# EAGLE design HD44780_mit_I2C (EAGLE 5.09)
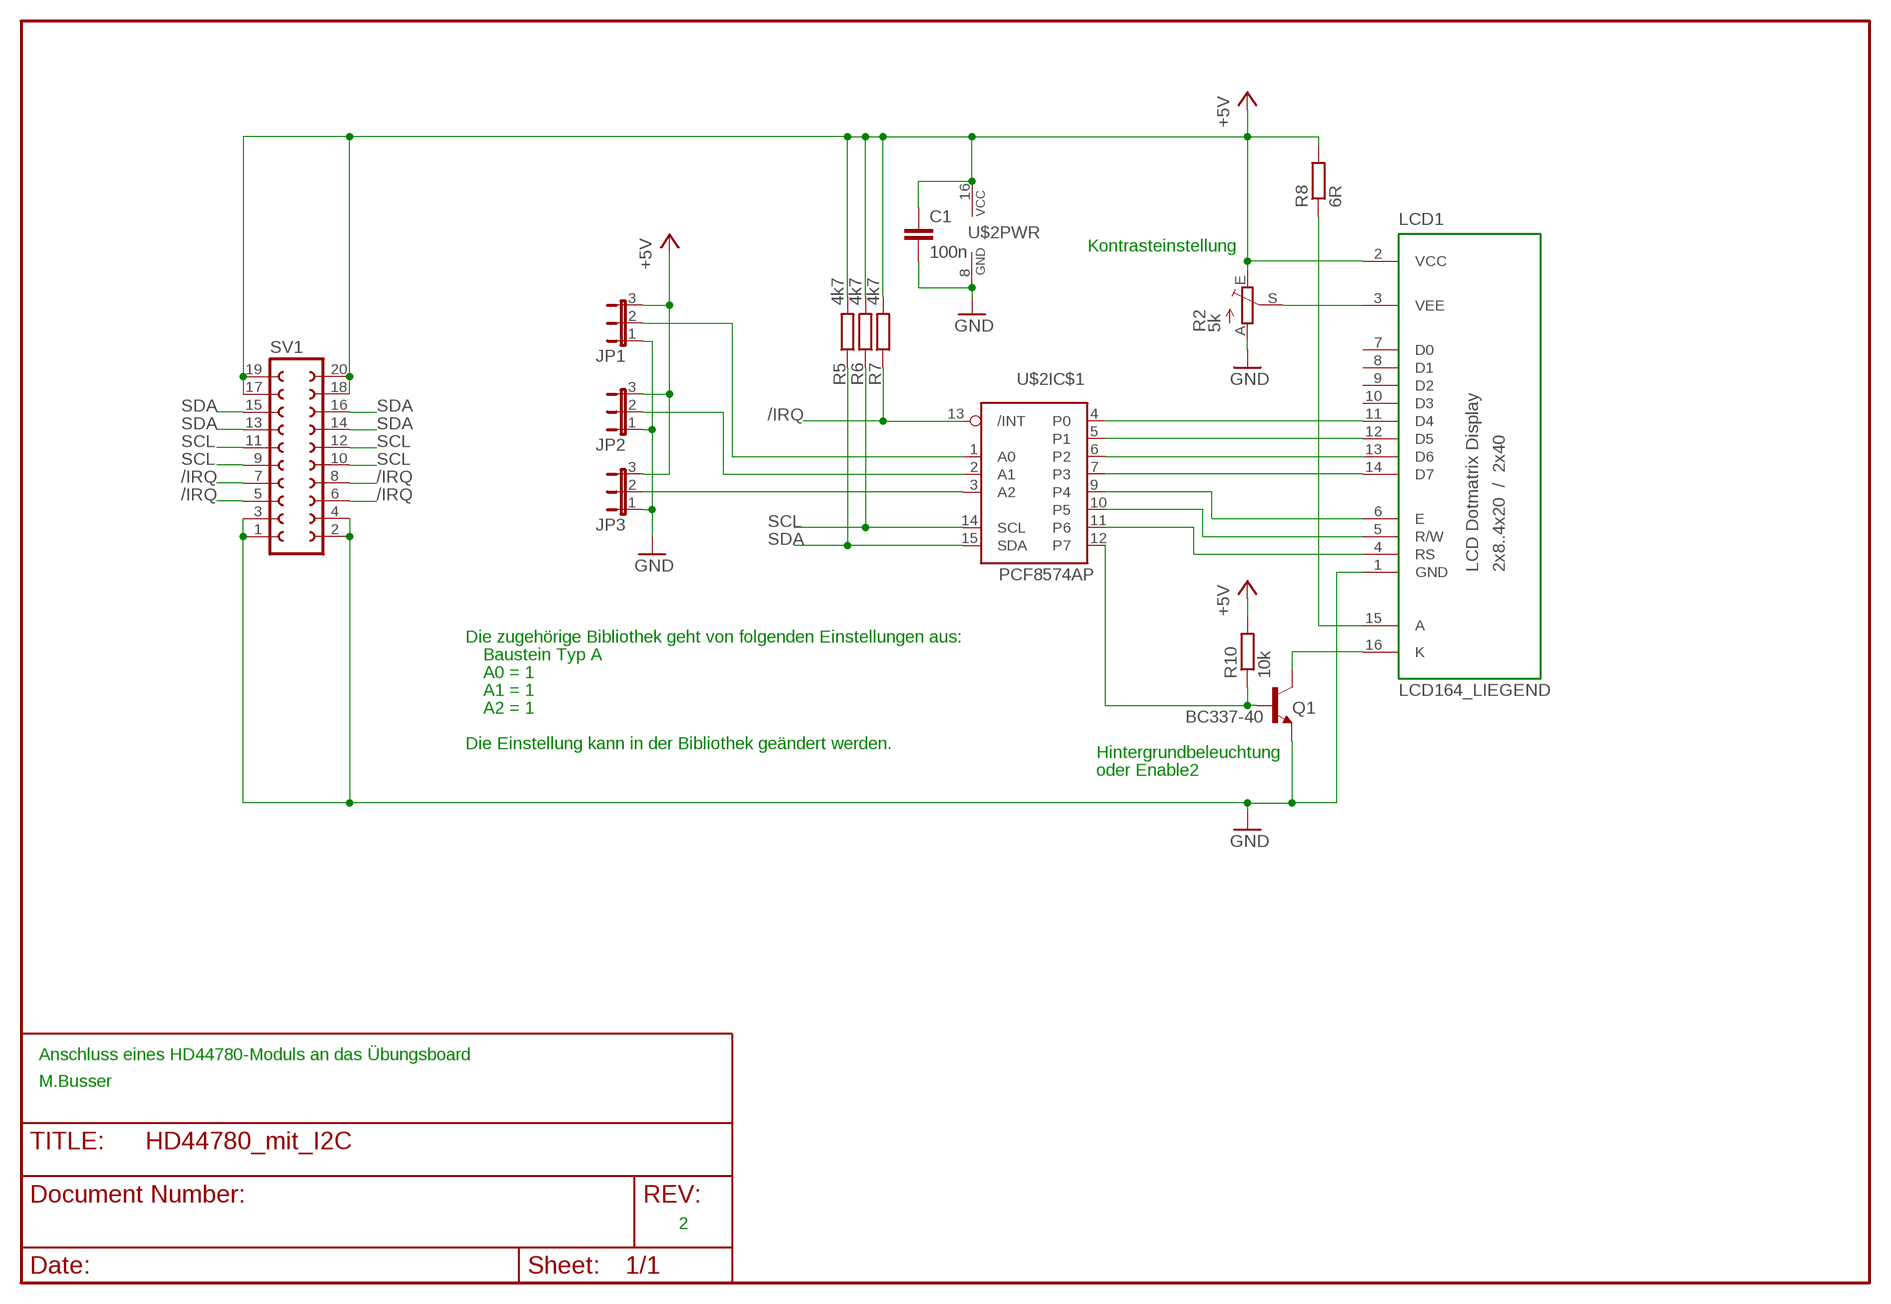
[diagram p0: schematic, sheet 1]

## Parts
C1  100n  C-EU050-025X075  [C050-025X075]
JP1  JP2E  [JP2]
JP2  JP2E  [JP2]
JP3  JP2E  [JP2]
LCD1  LCD164_LIEGEND  [LCD_164_LIEGEND]
Q1  BC337-40  [TO92]
R2  5k  TRIM_EU-B90P  [SP19L]
R5  4k7  R-EU_0207/10  [0207/10]
R6  4k7  R-EU_0207/10  [0207/10]
R7  4k7  R-EU_0207/10  [0207/10]
R8  6R  R-EU_0207/10  [0207/10]
R10  10k  R-EU_0207/10  [0207/10]
SV1  FE10-2  [FE10-2]
U$2  PCF8574AP  [DIL16]

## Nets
+5V: C1.1 JP1.3 JP2.3 JP3.3 LCD1.2(VCC) R2.E R5.2 R6.2 R7.2 R8.2 R10.2 SV1.17 SV1.18 SV1.19 SV1.20 U$2.16(PWR:VCC)
/IRQ: R7.1 SV1.5 SV1.6 SV1.7 SV1.8 U$2.13(IC$1:/INT)
A0: JP1.2 U$2.1(IC$1:A0)
A1: JP2.2 U$2.2(IC$1:A1)
A2: JP3.2 U$2.3(IC$1:A2)
GND: C1.2 JP1.1 JP2.1 JP3.1 LCD1.1(GND) Q1.1(E) R2.A SV1.1 SV1.2 SV1.3 SV1.4 U$2.8(PWR:GND)
N$1: LCD1.3(VEE) R2.S
N$2: LCD1.15(A) R8.1
N$3: LCD1.16(K) Q1.3(C)
N$5: LCD1.11(D4) U$2.4(IC$1:P0)
N$6: Q1.2(B) R10.1 U$2.12(IC$1:P7)
N$7: LCD1.4(RS) U$2.11(IC$1:P6)
N$11: LCD1.12(D5) U$2.5(IC$1:P1)
N$12: LCD1.13(D6) U$2.6(IC$1:P2)
N$13: LCD1.14(D7) U$2.7(IC$1:P3)
N$15: LCD1.6(E) U$2.9(IC$1:P4)
N$16: LCD1.5(R/W) U$2.10(IC$1:P5)
SCL: R6.1 SV1.9 SV1.10 SV1.11 SV1.12 U$2.14(IC$1:SCL)
SDA: R5.1 SV1.13 SV1.14 SV1.15 SV1.16 U$2.15(IC$1:SDA)
Unconnected: LCD1.7(D0) LCD1.8(D1) LCD1.9(D2) LCD1.10(D3)

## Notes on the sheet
- Kontrasteinstellung
- Die zugehörige Bibliothek geht von folgenden Einstellungen aus:
- Baustein Typ A
- A0 = 1
- A1 = 1
- A2 = 1
- Die Einstellung kann in der Bibliothek geändert werden.
- Hintergrundbeleuchtung
- oder Enable2
- Anschluss eines HD44780-Moduls an das Übungsboard
- M.Busser
- 2

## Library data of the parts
C1 = bbstghs:C-EU: CAPACITOR, European symbol
JP1-JP3 = jumper:JP2E: JUMPER
LCD1 = ibb:LCD164_LIEGEND
Q1 = bbstghs:BC337*: NPN Transistor
R2 = pot:TRIM_EU-: POTENTIOMETER
R5-R8 R10 = bbstghs:R-EU_: RESISTOR, European symbol
SV1 = con-lsta:FE10-2: FEMALE HEADER
U$2 = i2c:PCF8574: Remote 8-Bit I/O Expander for I²C Bus

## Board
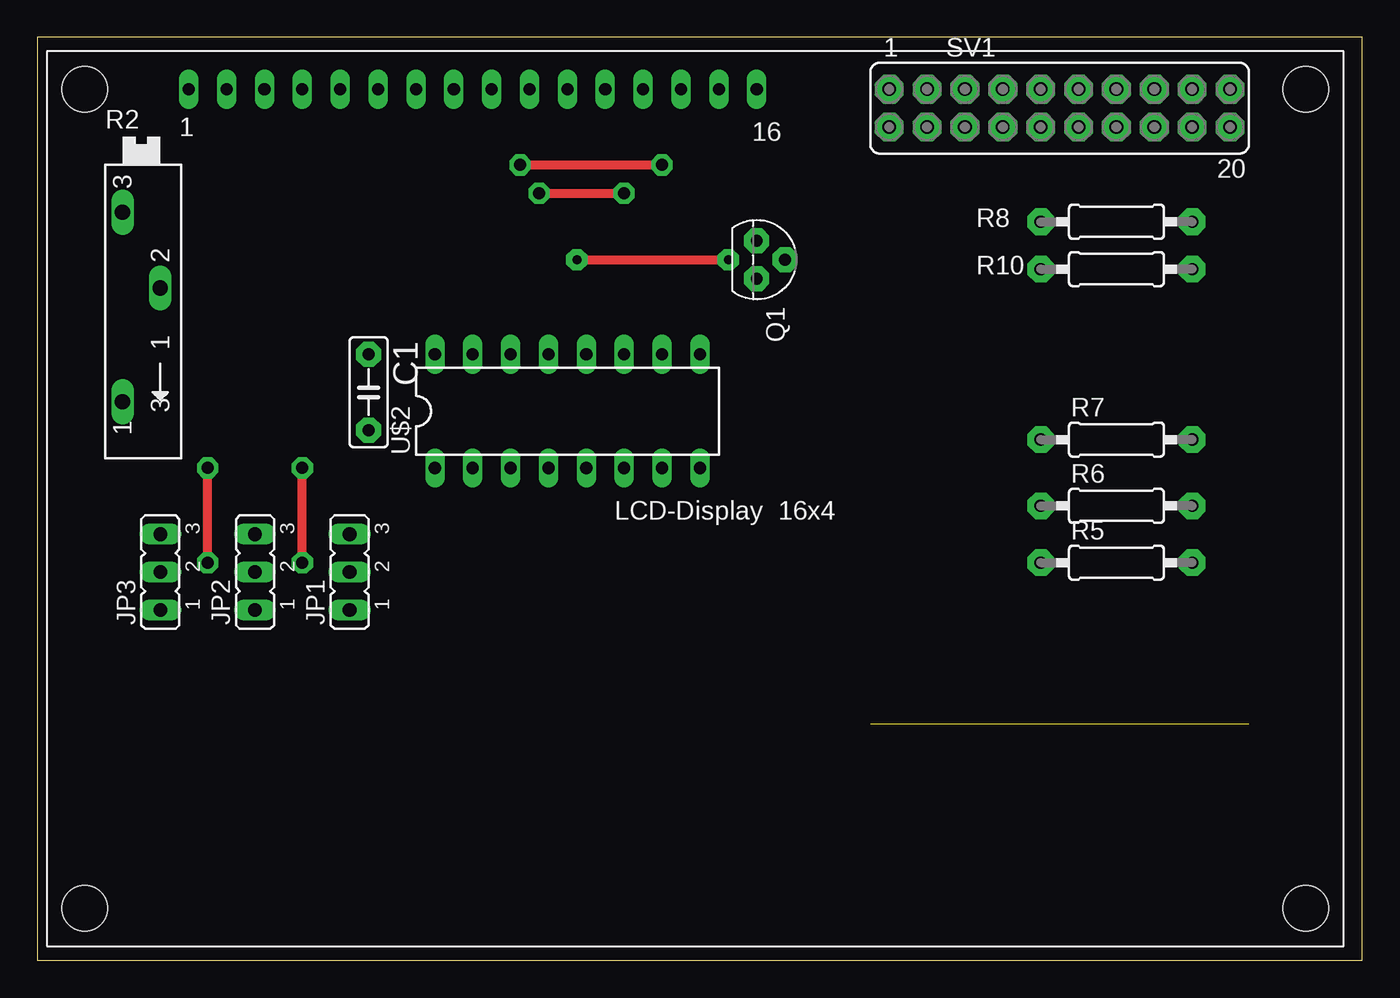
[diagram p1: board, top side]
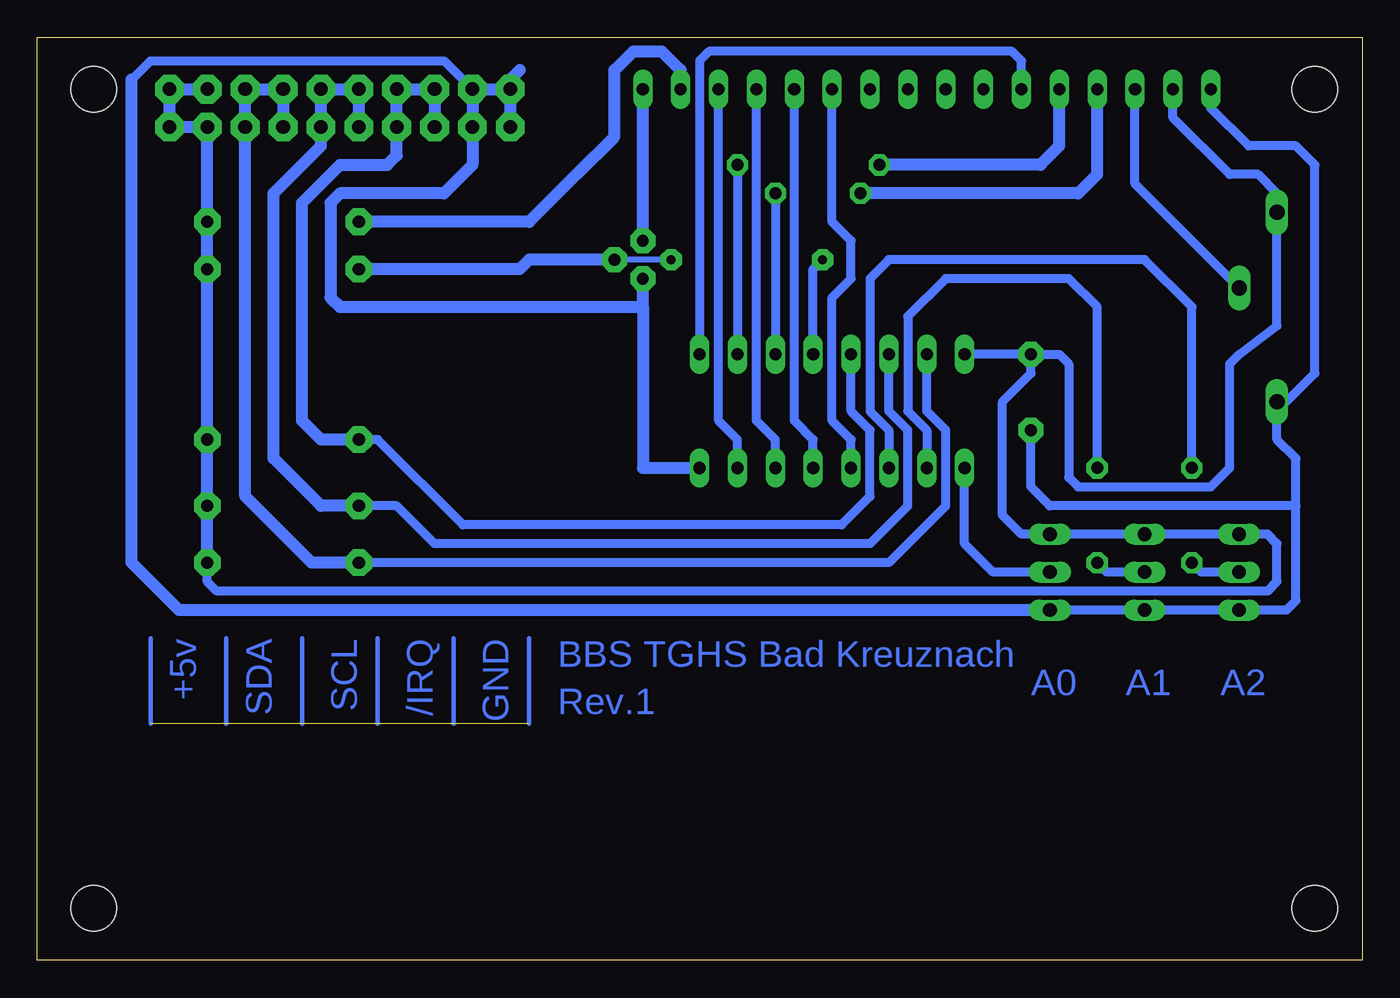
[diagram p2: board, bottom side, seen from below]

Size 88.88 x 61.9 mm. Coordinates in mm from the lower left corner, seen from the top.
Outline: 0,0 88.88,0 88.88,61.9 0,61.9 0,0
Copper layers (1*16): Top 0.035mm / dielectric 1.5mm / Bottom 0.035mm
Design rules "default": minimum track width 10mil, minimum drill 24mil, track to track 8mil, track to pad 8mil, pad to pad 8mil, via to via 8mil, smd to smd 8mil, copper to edge 40mil, drill to drill 8mil, minimum pad ring 10mil, minimum via ring 8mil, stop-mask expansion 4mil, vias tented up to drill 0mil, thermal gap 10mil

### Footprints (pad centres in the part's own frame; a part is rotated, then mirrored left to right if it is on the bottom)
C050-025X075 = drill 0.813 pad 1.676 octagon: 1 -2.54,0; 2 2.54,0
JP2 = drill 0.914 long: 1 -2.54,0; 2 0,0; 3 2.54,0
LCD_164_LIEGEND = drill 0.813 long: 1 -20.32,0; 2 -17.78,0; 3 -15.24,0; 4 -12.7,0; 5 -10.16,0; 6 -7.62,0; 7 -5.08,0; 8 -2.54,0; 9 0,0; 10 2.54,0; 11 5.08,0; 12 7.62,0; 13 10.16,0; 14 12.7,0; 15 15.24,0; 16 17.78,0 | hole 3.048: -27.305,0; 54.61,0; -27.305,-54.928; 54.61,-54.928
TO92 = drill 0.8 pad 1.676 octagon: 1 1.27,0; 2 0,1.905; 3 -1.27,0
SP19L = drill 1.016 long: A 5.715,-1.27; E -6.985,-1.27; S -1.905,1.27
0207/10 = drill 0.813 pad 1.778 octagon: 1 -5.08,0; 2 5.08,0
FE10-2 = drill 0.914 pad 1.93 octagon: 1 -11.43,1.27; 2 -11.43,-1.27; 3 -8.89,1.27; 4 -8.89,-1.27; 5 -6.35,1.27; 6 -6.35,-1.27; 7 -3.81,1.27; 8 -3.81,-1.27; 9 -1.27,1.27; 10 -1.27,-1.27; 11 1.27,1.27; 12 1.27,-1.27; 13 3.81,1.27; 14 3.81,-1.27; 15 6.35,1.27; 16 6.35,-1.27; 17 8.89,1.27; 18 8.89,-1.27; 19 11.43,1.27; 20 11.43,-1.27
DIL16 = drill 0.813 long: 1 -8.89,-3.81; 2 -6.35,-3.81; 3 -3.81,-3.81; 4 -1.27,-3.81; 5 1.27,-3.81; 6 3.81,-3.81; 7 6.35,-3.81; 8 8.89,-3.81; 9 8.89,3.81; 10 6.35,3.81; 11 3.81,3.81; 12 1.27,3.81; 13 -1.27,3.81; 14 -3.81,3.81; 15 -6.35,3.81; 16 -8.89,3.81

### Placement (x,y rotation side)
C1  22.23,38.1 270 top
JP1  20.95,26.04 90 top
JP2  14.61,26.04 90 top
JP3  8.26,26.04 90 top
LCD1  30.48,58.42 0 top
Q1  48.26,46.99 270 top
R2  6.99,43.18 270 top
R5  72.39,26.67 0 top
R6  72.39,30.48 0 top
R7  72.39,34.92 0 top
R8  72.39,49.53 0 top
R10  72.39,46.35 0 top
SV1  68.58,57.15 0 top
U$2  35.56,36.83 0 top

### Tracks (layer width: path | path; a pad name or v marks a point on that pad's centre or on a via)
+5V
  Bottom 0.61: LCD1.2 12.7,56.52 8.89,52.7 6.99,52.7 5.71,51.44 R2.E 5.71,42.55 8.26,40.64 8.89,40.01 8.89,33.02 10.16,31.75 19.05,31.75 19.68,32.38 19.68,40.01 20.32,40.64 C1.1 | C1.1 U$2.16 | R5.2 77.47,25.4 76.83,24.77 6.35,24.77 5.71,25.4 5.71,27.94 6.35,28.57 JP3.3 | JP3.3 JP2.3 JP1.3 22.86,28.57 24.13,29.84 24.13,37.47 22.23,39.37 C1.1 | JP3.3 6.99,28.57
  Bottom 0.813: R5.2 R6.2 R7.2 R10.2 R8.2 SV1.18 SV1.20 SV1.19 SV1.17
/IRQ
  Bottom 0.61: U$2.13 34.29,36.83 33.02,35.56 33.02,31.11 34.92,29.21 60.33,29.21 66.04,34.92 R7.1
  Bottom 0.813: R7.1 69.85,34.92 71.12,36.2 71.12,50.8 68.58,53.34 65.41,53.34 64.77,53.98 SV1.8 SV1.7 SV1.5 SV1.6
A0
  Bottom 0.61: JP1.2 24.77,26.04 26.67,27.94 U$2.1
A1  (via drill 0.8 pad 1.42)
  Top 0.61: v17.78,26.67 v17.78,33.02
  Bottom 0.61: U$2.2 29.21,35.56 30.48,36.83 30.48,43.18 27.94,45.72 19.68,45.72 17.78,43.81 v17.78,33.02 | JP2.2 17.14,26.04 v17.78,26.67
A2  (via drill 0.8 pad 1.42)
  Top 0.61: v11.43,26.67 v11.43,33.02
  Bottom 0.61: U$2.3 31.75,35.56 33.02,36.83 33.02,45.72 31.75,46.99 14.61,46.99 11.43,43.81 v11.43,33.02 | JP3.2 10.79,26.04 v11.43,26.67
GND
  Bottom 0.61: LCD1.1 10.16,57.15 7.62,54.61 4.45,54.61 3.17,53.34 3.17,39.37 5.08,37.47 R2.A 5.71,34.92 4.45,33.66 4.45,30.48 | SV1.1 57.15,59.05 | Q1.1 48.26,45.09 | SV1.3 61.59,60.33 81.28,60.33 82.55,59.05 | JP1.1 JP2.1 JP3.1 5.08,23.5 4.45,24.13 4.45,30.48 | C1.2 22.23,31.75 20.95,30.48 4.45,30.48
  Bottom 0.813: SV1.2 SV1.1 SV1.3 SV1.4 59.69,53.34 61.59,51.44 68.58,51.44 69.22,50.8 69.22,44.45 68.58,43.81 48.26,43.81 | 57.15,59.05 56.52,59.69 | 48.26,43.81 Q1.1 | 48.26,43.81 48.26,33.02 U$2.8 | 82.55,59.05 82.55,26.67 79.38,23.5 JP1.1
N$1
  Bottom 0.61: R2.S 15.24,52.07 LCD1.3
N$2
  Bottom 0.61: R8.1 64.77,49.53
  Bottom 0.813: LCD1.15 45.72,59.69 46.99,60.96 48.9,60.96 50.16,59.69 50.16,55.24 52.7,52.7 55.88,49.53 R8.1
N$3
  Bottom 0.813: Q1.3 LCD1.16
N$5
  Bottom 0.61: U$2.4 34.29,34.92 35.56,36.2 35.56,44.45 34.29,45.72 34.29,48.26 35.56,49.53 LCD1.11
N$6  (via drill 0.6 pad 1.42)
  Top 0.61: v36.2,46.99 v46.35,46.99
  Bottom 0.406: v46.35,46.99 Q1.2
  Bottom 0.61: U$2.12 36.83,46.35 v36.2,46.99
  Bottom 0.813: Q1.2 55.88,46.99 56.52,46.35 R10.1
N$7  (via drill 0.8 pad 1.42)
  Top 0.61: v33.66,51.44 v39.37,51.44
  Bottom 0.61: v39.37,51.44 U$2.11
  Bottom 0.813: LCD1.4 17.78,52.7 19.05,51.44 v33.66,51.44
N$8  (5 unrouted)
  Bottom 0.305: 60.96,15.88 60.96,21.59 | 66.04,15.88 66.04,21.59 | 71.12,15.88 71.12,21.59 | 76.2,15.88 76.2,21.59 | 81.28,15.88 81.28,21.59 | 55.88,15.88 55.88,21.59
N$11
  Bottom 0.61: U$2.5 36.83,34.92 38.1,36.2 LCD1.12
N$12
  Bottom 0.61: U$2.6 39.37,34.92 40.64,36.2 LCD1.13
N$13
  Bottom 0.61: U$2.7 41.91,34.92 43.18,36.2 LCD1.14
N$15
  Bottom 0.61: U$2.9 44.45,60.33 43.81,60.96 23.5,60.96 22.86,60.33 LCD1.6
N$16  (via drill 0.8 pad 1.42)
  Top 0.61: v32.38,53.34 v41.91,53.34
  Bottom 0.61: v41.91,53.34 U$2.10
  Bottom 0.813: LCD1.5 20.32,54.61 21.59,53.34 v32.38,53.34
SCL
  Bottom 0.61: U$2.14 31.75,36.83 30.48,35.56 30.48,30.48 33.02,27.94 62.23,27.94 64.77,30.48 R6.1
  Bottom 0.813: R6.1 69.85,30.48 73.03,33.66 73.03,51.44 69.85,54.61 SV1.12 SV1.11 SV1.9 SV1.10
SDA
  Bottom 0.61: U$2.15 29.21,36.83 27.94,35.56 27.94,30.48 31.75,26.67 R5.1
  Bottom 0.813: R5.1 70.48,26.67 74.93,31.11 SV1.16 SV1.15 SV1.13 SV1.14

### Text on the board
Bottom: GND | /IRQ | SCL | SDA | +5v | BBS TGHS Bad Kreuznach | A2 | A1 | A0 | Rev.1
